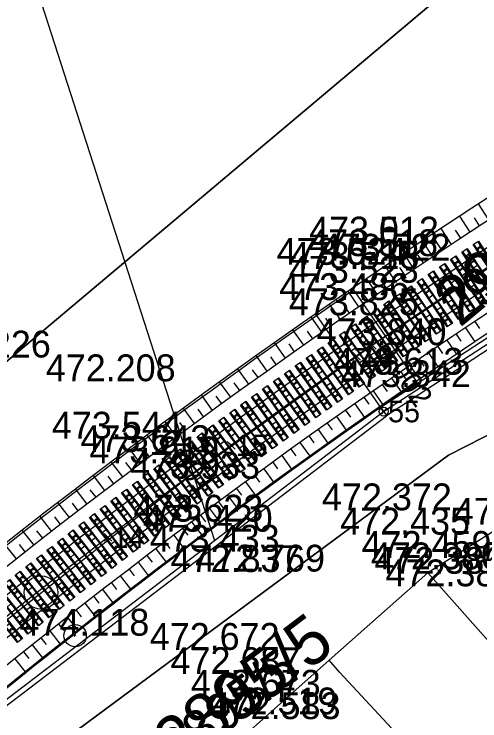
# Model space of a CAD drawing. Extents: x -758836 to -757729, y -1175316 to -1174366.
# Drawn here: x -758387.77 to -758366.97, y -1174833.52 to -1174801.92 of the extents above; entities that cross this region are included whole.
import ezdxf

# ---------------------------------------------------------------- set-up
doc = ezdxf.new("R2010")
doc.units = 0
for name, color, linetype in [('_NOR-body-stávající osa', 7, 'Continuous'), ('_NOR-návrh tenká', 7, 'Continuous'), ('_NOR-osa', 7, 'Continuous'), ('_NOR-popis', 7, 'Continuous'), ('_NOR-posuny', 7, 'Continuous'), ('_NOR-pražce', 7, 'Continuous'), ('_NOR-sanace', 7, 'Continuous'), ('_NOR-svahy', 7, 'Continuous'), ('_NOR-vytyčení', 7, 'Continuous'), ('_vytyčený bod', 7, 'Continuous'), ('G_Obvod stavby', 7, 'Continuous'), ('Hranice parcel', 7, 'Continuous'), ('Parcelní čísla', 7, 'Continuous'), ('Vnitřní kresba', 7, 'Continuous'), ('Vrstva 1', 7, 'Continuous'), ('Vrstva 61', 7, 'Continuous'), ('Vrstva 7', 7, 'Continuous')]:
    doc.layers.add(name, color=color, linetype=linetype)

# ---------------------------------------------------------------- blocks, each defined once
blk = doc.blocks.new('C093')
at = {"layer": 'Vrstva 7'}
blk.add_line((-0.05, 0), (0.05, 0), dxfattribs=at)
blk.add_circle((0, 0), 0.5, dxfattribs=at)
blk = doc.blocks.new('C513')
at = {"layer": 'Vrstva 7'}
blk.add_circle((0, 0), 0.75, dxfattribs=at)
blk = doc.blocks.new('půdorys-SB8')
at = {"layer": '_NOR-pražce'}
for p, q in [((-1.21, 0.109), (-0.96, 0.095)), ((-0.96, 0.095), (-0.56, 0.099)), ((-0.96, 0.095), (-0.96, -0.095)), ((-0.56, 0.099), (-0.32, 0.109)), ((-0.56, 0.099), (-0.56, -0.1)), ((-0.32, 0.109), (0.32, 0.109)), ((-0.32, 0.109), (-0.32, -0.11)), ((0.56, 0.099), (0.32, 0.109)), ((0.32, -0.11), (0.32, 0.109)), ((0.96, 0.095), (0.56, 0.099)), ((0.56, 0.099), (0.56, -0.1)), ((1.21, 0.109), (0.96, 0.095)), ((0.96, 0.095), (0.96, -0.095)), ((-1.21, -0.11), (-0.96, -0.095)), ((-0.96, -0.095), (-0.56, -0.1)), ((-0.56, -0.1), (-0.32, -0.11)), ((-0.32, -0.11), (0.32, -0.11)), ((0.56, -0.1), (0.32, -0.11)), ((0.96, -0.095), (0.56, -0.1)), ((1.21, -0.11), (0.96, -0.095))]:
    blk.add_line(p, q, dxfattribs=at)
blk.add_lwpolyline([(-1.21, 0.142), (1.21, 0.142), (1.21, -0.142), (-1.21, -0.142)], close=True, dxfattribs=at)
for centre in [(-0.916, 0.048), (-0.604, 0.048), (0.604, 0.048), (0.916, 0.048), (-0.916, -0.048), (-0.604, -0.048), (0.604, -0.048), (0.916, -0.048)]:
    blk.add_circle(centre, 0.015, dxfattribs=at)
blk = doc.blocks.new('POINT_DISPLAY')
for p, q in [((-0.175, -0.175), (0.175, 0.175)), ((-0.175, 0.175), (0.175, -0.175))]:
    blk.add_line(p, q)

msp = doc.modelspace()

# ---------------------------------------------------------------- linework, layer by layer
at = {"layer": '_NOR-návrh tenká'}
for p, q in [((-758356.34, -1174809.692), (-758371.395, -1174819.503)), ((-758371.266, -1174819.688), (-758356.223, -1174809.884)), ((-758356.106, -1174810.077), (-758371.14, -1174819.874)), ((-758371.395, -1174819.503), (-758371.138, -1174819.872)), ((-758391.422, -1174835.079), (-758371.266, -1174819.688)), ((-758391.278, -1174835.252), (-758371.14, -1174819.874))]:
    msp.add_line(p, q, dxfattribs=at)
msp.add_circle((-758371.266, -1174819.688), 0.2, dxfattribs=at)
for radius, start, end in [(295.6, 97.09776, 129.28488), (294.75, 97.0979, 129.28474), (291.3, 97.09848, 129.28417), (290.55, 97.09861, 129.28404), (293.75, 120.96729, 129.28457), (292.25, 120.96729, 129.28432)]:
    msp.add_arc((-758205.34, -1175057.864), radius, start, end, dxfattribs=at)
at = {"layer": '_NOR-osa'}
msp.add_arc((-758205.34, -1175057.864), 293, 97.09819, 129.28445, dxfattribs=at)
at = {"layer": '_NOR-popis'}
msp.add_lwpolyline([(-758388.955, -1174762.992), (-758397.997, -1174765.904), (-758378.816, -1174825.453)], dxfattribs=at)
at = {"layer": '_NOR-sanace'}
for p, q in [((-758369.764, -1174818.375), (-758372.594, -1174814.253)), ((-758371.395, -1174819.503), (-758374.253, -1174815.4))]:
    msp.add_line(p, q, dxfattribs=at)
for radius, end in [(295.5, 129.28486), (290.5, 129.28403)]:
    msp.add_arc((-758205.34, -1175057.864), radius, 124.47202, end, dxfattribs=at)
at = {"layer": '_NOR-svahy'}
for points in [[(-758366.56, -1174811.114), (-758367.025, -1174810.402)], [(-758367.396, -1174811.662), (-758367.863, -1174810.952)], [(-758366.978, -1174811.388), (-758367.211, -1174811.032)], [(-758368.23, -1174812.213), (-758368.7, -1174811.505)], [(-758367.814, -1174811.938), (-758368.048, -1174811.583)], [(-758369.063, -1174812.768), (-758369.535, -1174812.061)], [(-758368.647, -1174812.49), (-758368.882, -1174812.136)], [(-758369.894, -1174813.324), (-758370.368, -1174812.619)], [(-758369.478, -1174813.046), (-758369.715, -1174812.693)], [(-758370.722, -1174813.884), (-758371.199, -1174813.18)], [(-758370.308, -1174813.604), (-758370.546, -1174813.252)], [(-758371.549, -1174814.447), (-758372.028, -1174813.745)], [(-758371.136, -1174814.165), (-758371.375, -1174813.814)], [(-758372.374, -1174815.012), (-758372.856, -1174814.312)], [(-758371.962, -1174814.729), (-758372.202, -1174814.378)], [(-758373.197, -1174815.58), (-758373.681, -1174814.881)], [(-758372.786, -1174815.296), (-758373.027, -1174814.946)], [(-758374.018, -1174816.151), (-758374.504, -1174815.454)], [(-758373.608, -1174815.865), (-758373.85, -1174815.516)], [(-758367.191, -1174815.666), (-758366.983, -1174815.978)], [(-758374.837, -1174816.725), (-758375.326, -1174816.029)], [(-758374.428, -1174816.437), (-758374.672, -1174816.089)], [(-758367.607, -1174815.944), (-758367.189, -1174816.567)], [(-758368.436, -1174816.503), (-758368.016, -1174817.124)], [(-758368.022, -1174816.223), (-758367.812, -1174816.534)], [(-758375.654, -1174817.301), (-758376.145, -1174816.607)], [(-758375.246, -1174817.012), (-758375.491, -1174816.665)], [(-758368.85, -1174816.783), (-758368.64, -1174817.094)], [(-758369.264, -1174817.064), (-758368.842, -1174817.684)], [(-758376.469, -1174817.88), (-758376.963, -1174817.188)], [(-758376.062, -1174817.59), (-758376.308, -1174817.244)], [(-758369.677, -1174817.346), (-758369.466, -1174817.656)], [(-758377.283, -1174818.462), (-758377.778, -1174817.772)], [(-758370.09, -1174817.628), (-758369.665, -1174818.247)], [(-758376.876, -1174818.171), (-758377.124, -1174817.825)], [(-758370.502, -1174817.911), (-758370.289, -1174818.22)], [(-758378.094, -1174819.047), (-758378.592, -1174818.358)], [(-758377.688, -1174818.754), (-758377.937, -1174818.409)], [(-758370.913, -1174818.195), (-758370.487, -1174818.812)], [(-758371.325, -1174818.48), (-758371.111, -1174818.788)], [(-758378.903, -1174819.634), (-758379.404, -1174818.947)], [(-758378.499, -1174819.34), (-758378.748, -1174818.996)], [(-758371.735, -1174818.765), (-758371.307, -1174819.381)], [(-758372.555, -1174819.338), (-758372.124, -1174819.952)], [(-758372.145, -1174819.051), (-758371.931, -1174819.359)], [(-758379.71, -1174820.225), (-758380.213, -1174819.539)], [(-758379.307, -1174819.929), (-758379.558, -1174819.586)], [(-758372.964, -1174819.625), (-758372.748, -1174819.932)], [(-758373.373, -1174819.913), (-758372.94, -1174820.526)], [(-758380.515, -1174820.818), (-758381.021, -1174820.134)], [(-758380.113, -1174820.521), (-758380.365, -1174820.178)], [(-758373.781, -1174820.202), (-758373.564, -1174820.508)], [(-758374.189, -1174820.491), (-758373.754, -1174821.103)], [(-758381.319, -1174821.413), (-758381.826, -1174820.731)], [(-758380.917, -1174821.115), (-758381.171, -1174820.774)], [(-758374.596, -1174820.782), (-758374.378, -1174821.087)], [(-758375.003, -1174821.072), (-758374.566, -1174821.682)], [(-758382.12, -1174822.012), (-758382.63, -1174821.331)], [(-758381.72, -1174821.712), (-758381.974, -1174821.372)], [(-758375.409, -1174821.364), (-758375.19, -1174821.668)], [(-758375.814, -1174821.656), (-758375.376, -1174822.264)], [(-758382.919, -1174822.613), (-758383.431, -1174821.934)], [(-758382.52, -1174822.312), (-758382.775, -1174821.972)], [(-758376.22, -1174821.949), (-758376, -1174822.253)], [(-758376.624, -1174822.243), (-758376.183, -1174822.85)], [(-758383.716, -1174823.217), (-758384.231, -1174822.54)], [(-758383.318, -1174822.914), (-758383.575, -1174822.576)], [(-758377.432, -1174822.832), (-758376.989, -1174823.437)], [(-758377.029, -1174822.537), (-758376.807, -1174822.84)], [(-758384.511, -1174823.823), (-758385.028, -1174823.148)], [(-758377.835, -1174823.128), (-758377.613, -1174823.43)], [(-758384.114, -1174823.519), (-758384.372, -1174823.182)], [(-758378.238, -1174823.424), (-758377.793, -1174824.028)], [(-758385.304, -1174824.432), (-758385.823, -1174823.759)], [(-758378.64, -1174823.722), (-758378.417, -1174824.023)], [(-758384.908, -1174824.127), (-758385.167, -1174823.79)], [(-758379.042, -1174824.019), (-758378.595, -1174824.621)], [(-758386.095, -1174825.044), (-758386.616, -1174824.373)], [(-758385.7, -1174824.738), (-758385.96, -1174824.402)], [(-758379.443, -1174824.318), (-758379.219, -1174824.619)], [(-758379.844, -1174824.617), (-758379.394, -1174825.218)], [(-758386.884, -1174825.659), (-758387.408, -1174824.989)], [(-758386.49, -1174825.351), (-758386.751, -1174825.016)], [(-758380.244, -1174824.917), (-758380.018, -1174825.217)], [(-758380.643, -1174825.217), (-758380.192, -1174825.816)], [(-758387.671, -1174826.276), (-758388.197, -1174825.608)], [(-758387.278, -1174825.967), (-758387.54, -1174825.633)], [(-758381.042, -1174825.519), (-758380.816, -1174825.818)], [(-758381.441, -1174825.821), (-758380.987, -1174826.418)], [(-758381.839, -1174826.123), (-758381.612, -1174826.422)], [(-758382.236, -1174826.427), (-758381.781, -1174827.022)], [(-758382.633, -1174826.731), (-758382.405, -1174827.028)], [(-758383.03, -1174827.035), (-758382.572, -1174827.629)], [(-758383.426, -1174827.341), (-758383.197, -1174827.637)], [(-758383.821, -1174827.647), (-758383.362, -1174828.239)], [(-758384.216, -1174827.953), (-758383.986, -1174828.249)], [(-758384.61, -1174828.261), (-758384.149, -1174828.852)], [(-758385.004, -1174828.569), (-758384.773, -1174828.864)], [(-758385.398, -1174828.877), (-758384.934, -1174829.467)], [(-758385.79, -1174829.187), (-758385.558, -1174829.481)], [(-758386.183, -1174829.497), (-758385.717, -1174830.085)], [(-758386.574, -1174829.808), (-758386.341, -1174830.101)], [(-758386.965, -1174830.119), (-758386.498, -1174830.705)], [(-758387.356, -1174830.431), (-758387.122, -1174830.724)], [(-758387.746, -1174830.744), (-758387.277, -1174831.329)]]:
    msp.add_lwpolyline(points, dxfattribs=at)
at = {"layer": '_vytyčený bod'}
for p, q in [((-758372.476, -1174817.21), (-758372.576, -1174817.11)), ((-758372.476, -1174817.21), (-758372.376, -1174817.11)), ((-758372.476, -1174817.21), (-758372.576, -1174817.31)), ((-758372.476, -1174817.21), (-758372.376, -1174817.31)), ((-758371.266, -1174819.688), (-758371.366, -1174819.588)), ((-758371.266, -1174819.688), (-758371.166, -1174819.588)), ((-758371.266, -1174819.688), (-758371.366, -1174819.788)), ((-758371.266, -1174819.688), (-758371.166, -1174819.788)), ((-758378.076, -1174821.197), (-758378.176, -1174821.097)), ((-758378.076, -1174821.197), (-758378.176, -1174821.297)), ((-758378.076, -1174821.197), (-758377.976, -1174821.097)), ((-758378.076, -1174821.197), (-758377.976, -1174821.297)), ((-758383.58, -1174825.314), (-758383.68, -1174825.214)), ((-758383.58, -1174825.314), (-758383.68, -1174825.414)), ((-758383.58, -1174825.314), (-758383.48, -1174825.214)), ((-758383.58, -1174825.314), (-758383.48, -1174825.414))]:
    msp.add_line(p, q, dxfattribs=at)
at = {"layer": 'G_Obvod stavby'}
msp.add_lwpolyline([(-758392.72, -1174840.756), (-758391.23, -1174838.56), (-758368.37, -1174821.64), (-758340.31, -1174807.33), (-758320.27, -1174796.89), (-758301, -1174790.21), (-758267.96, -1174782.93), (-758224.96, -1174775.27), (-758184.87, -1174772.83), (-758142.71, -1174770.26), (-758089.84, -1174768.68), (-758106.02, -1174731.44), (-758149.09, -1174725.67), (-758199.62, -1174726.6), (-758225.76, -1174732.36), (-758252.17, -1174738.18), (-758254.97, -1174739.34), (-758266.58, -1174744.16), (-758279.45, -1174749.49), (-758302.42, -1174759.02), (-758331.68, -1174770.24), (-758367.17, -1174799.81), (-758405.64, -1174832.2)], dxfattribs=at)
at = {"layer": 'Hranice parcel'}
msp.add_line((-758405.64, -1174832.2), (-758367.17, -1174799.81), dxfattribs=at)
for points in [[(-758340.31, -1174807.33), (-758368.37, -1174821.64), (-758391.23, -1174838.56)], [(-758352.89, -1174817.05), (-758365.77, -1174824.68), (-758369.29, -1174826.9), (-758373.7, -1174830.81), (-758376.95, -1174833.7), (-758377.89, -1174834.53), (-758384.91, -1174840.91)]]:
    msp.add_lwpolyline(points, dxfattribs=at)
at = {"layer": 'Vnitřní kresba'}
for p, q in [((-758369.29, -1174826.9), (-758358.97, -1174838.54)), ((-758373.23, -1174831.34), (-758373.7, -1174830.81)), ((-758373.23, -1174831.34), (-758363.1, -1174842.22))]:
    msp.add_line(p, q, dxfattribs=at)
at = {"layer": 'Vrstva 1'}
msp.add_lwpolyline([(-758443.817, -1174881.252), (-758441.673, -1174879.1), (-758423.412, -1174860.854), (-758412.446, -1174850.23), (-758405.322, -1174843.614), (-758399.028, -1174837.996), (-758392.64, -1174832.554), (-758380.106, -1174822.693), (-758371.773, -1174816.721), (-758363.37, -1174811.125), (-758354.46, -1174805.649), (-758345.526, -1174800.592), (-758336.614, -1174795.909), (-758327.338, -1174791.462), (-758317.813, -1174787.314), (-758307.666, -1174783.315), (-758298.059, -1174779.921), (-758285.017, -1174775.914), (-758275.047, -1174773.289)], dxfattribs=at)

# ---------------------------------------------------------------- block references
at = {"layer": '_NOR-body-stávající osa'}
for p in [(-758371.773, -1174816.721), (-758380.106, -1174822.693)]:
    msp.add_blockref('POINT_DISPLAY', p, dxfattribs=at)
at = {"layer": '_NOR-pražce'}
for p, rotation in [((-758366.487, -1174813.159), -56.63364048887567), ((-758366.987, -1174813.489), -56.51661078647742), ((-758367.485, -1174813.819), -56.399581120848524), ((-758367.984, -1174814.151), -56.28255145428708), ((-758368.481, -1174814.484), -56.1655217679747), ((-758368.978, -1174814.818), -56.048492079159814), ((-758369.474, -1174815.152), -55.93146241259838), ((-758369.969, -1174815.488), -55.814432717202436), ((-758370.464, -1174815.825), -55.69740305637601), ((-758370.958, -1174816.163), -55.58037335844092), ((-758371.451, -1174816.501), -55.46334371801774), ((-758371.944, -1174816.841), -55.34631401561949), ((-758372.436, -1174817.182), -55.229284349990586), ((-758372.927, -1174817.524), -55.112254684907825), ((-758373.418, -1174817.867), -54.99522498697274), ((-758373.908, -1174818.21), -54.878195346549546), ((-758374.397, -1174818.555), -54.76116564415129), ((-758374.885, -1174818.901), -54.64413597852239), ((-758375.373, -1174819.248), -54.52710631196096), ((-758375.86, -1174819.596), -54.41007662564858), ((-758376.346, -1174819.944), -54.29304696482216), ((-758376.832, -1174820.294), -54.17601726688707), ((-758377.317, -1174820.645), -54.05898762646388), ((-758377.801, -1174820.997), -53.941957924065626), ((-758378.285, -1174821.349), -53.82492826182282), ((-758378.767, -1174821.703), -53.70789860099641), ((-758379.249, -1174822.058), -53.59086890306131), ((-758379.731, -1174822.414), -53.47383926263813), ((-758380.211, -1174822.77), -53.356809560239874), ((-758380.691, -1174823.128), -53.239779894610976), ((-758381.17, -1174823.487), -53.12275022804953), ((-758381.648, -1174823.846), -53.0057205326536), ((-758382.126, -1174824.207), -52.88869087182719), ((-758382.603, -1174824.569), -52.771661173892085), ((-758383.079, -1174824.931), -52.6546315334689), ((-758383.554, -1174825.295), -52.53760183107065), ((-758384.029, -1174825.659), -52.42057216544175), ((-758384.503, -1174826.025), -52.303542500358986), ((-758384.976, -1174826.391), -52.18651280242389), ((-758385.449, -1174826.758), -52.06948316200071), ((-758385.92, -1174827.127), -51.95245345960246), ((-758386.391, -1174827.496), -51.83542379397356), ((-758386.861, -1174827.866), -51.71839412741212), ((-758387.331, -1174828.238), -51.60136444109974), ((-758387.799, -1174828.61), -51.48433478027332), ((-758388.267, -1174828.983), -51.36730508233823)]:
    msp.add_blockref('půdorys-SB8', p, dxfattribs=dict(at, rotation=rotation))
at = {"layer": '_NOR-vytyčení'}
for p in [(-758372.476, -1174817.21), (-758378.076, -1174821.197), (-758383.58, -1174825.314)]:
    msp.add_blockref('POINT_DISPLAY', p, dxfattribs=at)
at = {"layer": 'Vrstva 7', "rotation": 38.193547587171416}
for name, p in [('C513', (-758386.57, -1174827.778)), ('C093', (-758385.049, -1174829.708))]:
    msp.add_blockref(name, p, dxfattribs=at)

# ---------------------------------------------------------------- texts
at = {"layer": '_NOR-posuny'}
for s, rotation, p in [('0,002', 304.6128, (-758371.63, -1174816.928)), ('0,001', 306.6177, (-758381.415, -1174820.932))]:
    msp.add_text(s, height=0.9599, rotation=rotation, dxfattribs=at).set_placement(p)
at = {"layer": '_vytyčený bod'}
for s, height, p in [('16', 0.9599, (-758372.276, -1174817.69)), ('16', 0.9596, (-758372.276, -1174817.69)), ('55', 0.9599, (-758371.066, -1174820.168)), ('55', 0.9596, (-758371.066, -1174820.168)), ('15', 0.9599, (-758377.876, -1174821.677)), ('15', 0.9596, (-758377.876, -1174821.677)), ('14', 0.9599, (-758383.38, -1174825.794)), ('14', 0.9596, (-758383.38, -1174825.794))]:
    msp.add_text(s, height=height, dxfattribs=at).set_placement(p)
at = {"layer": 'Parcelní čísla'}
for s, height, rotation, p in [('2926/1', 2.1751, 40, (-758367.845, -1174815.948)), ('2926/1', 1.7, 40, (-758367.845, -1174815.948)), ('2895/5', 2.1751, 37, (-758380.458, -1174835.668)), ('2895/5', 1.7, 37, (-758380.458, -1174835.668))]:
    msp.add_text(s, height=height, rotation=rotation, dxfattribs=at).set_placement(p)
at = {"layer": 'Vrstva 61'}
for s, p in [('473.012', (-758374.598, -1174812.178)), ('473.512', (-758374.597, -1174812.178)), ('473.518', (-758374.634, -1174812.74)), ('473.522', (-758374.073, -1174812.942)), ('473.024', (-758376.046, -1174813.128)), ('473.524', (-758376.044, -1174813.127)), ('473.518', (-758375.466, -1174813.31)), ('473.523', (-758375.497, -1174813.93)), ('473.486', (-758375.928, -1174814.703)), ('473.825', (-758375.498, -1174815.383)), ('473.840', (-758374.258, -1174816.721)), ('474.226', (-758391.934, -1174817.272)), ('473.613', (-758373.507, -1174818.04)), ('472.208', (-758386.358, -1174818.333)), ('473.342', (-758373.17, -1174818.595)), ('473.544', (-758386.087, -1174820.899)), ('473.643', (-758384.811, -1174821.501)), ('473.919', (-758384.411, -1174822.004)), ('473.933', (-758382.591, -1174822.693)), ('472.372', (-758374.018, -1174824.103)), ('473.623', (-758382.442, -1174824.609)), ('472.197', (-758368.13, -1174824.749)), ('473.420', (-758382.024, -1174825.059)), ('472.435', (-758373.207, -1174825.191)), ('473.433', (-758381.715, -1174825.955)), ('472.459', (-758372.247, -1174826.232)), ('472.837', (-758380.78, -1174826.862)), ('472.769', (-758379.684, -1174826.842)), ('472.380', (-758371.829, -1174826.741)), ('472.386', (-758371.677, -1174826.94)), ('472.386', (-758371.179, -1174827.501)), ('474.118', (-758387.534, -1174829.708)), ('472.672', (-758381.716, -1174830.343)), ('472.687', (-758380.785, -1174831.426)), ('472.673', (-758379.876, -1174832.437)), ('472.519', (-758379.133, -1174833.226)), ('472.583', (-758378.992, -1174833.439))]:
    msp.add_text(s, height=1.2, dxfattribs=at).set_placement(p)

doc.saveas('drawing.dxf')
